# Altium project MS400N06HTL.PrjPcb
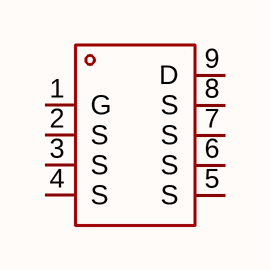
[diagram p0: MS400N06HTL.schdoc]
1 sheet, 1 parts. Net scope: global (net labels, ports and power ports of the same name join across sheets).

## Sheet MS400N06HTL.schdoc
size 127 x 101 mm

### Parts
Q?  ms400n06htl  [TOLL-8_L10.4-W9.9-P1.20-LS11.7-BL]  (value not drawn)

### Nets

Not connected (* = marked no-connect by the designer): Q? 1(G) 2(S) 3(S) 4(S) 5(S) 6(S) 7(S) 8(S) 9(D)

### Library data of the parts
Q? = ms400n06htl: 数量:1个N沟道;漏源电压(Vdss):60V;连续漏极电流(Id):400A;导通电阻(RDS(on)):1.2mΩ@10V;耗散功率(Pd):455W;阈值电压(Vgs(th)):2.9V;; Manufacturer: MSKSEMI(美森科); AddInBom: yes; ModelId: 8ca80fd5c5554dd79eeadaa9fc4e76f7; ModelName: TOLL_L10.4-W9.9-P1.20-LS11.7-BL_HUAYI_HYG022N10NS1TA; ModelTransform: 389.763,459.842,0,0,0,0,0,59.055,0; Number: 1个N沟道; Drain to Source Voltage: 60V; Current - Continuous Drain(Id): 400A; Pd - Power Dissipation: 455W; Gate Threshold Voltage (Vgs(th)): 2.9V; Gate Charge(Qg): 98nC; Input Capacitance(Ciss): 5.93nF; Reverse Transfer Capacitance (Crss@Vds): 85pF; Configuration: 独立式; Type: N沟道; Output Capacitance(Coss): 2.24nF; Vgs: ±20V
